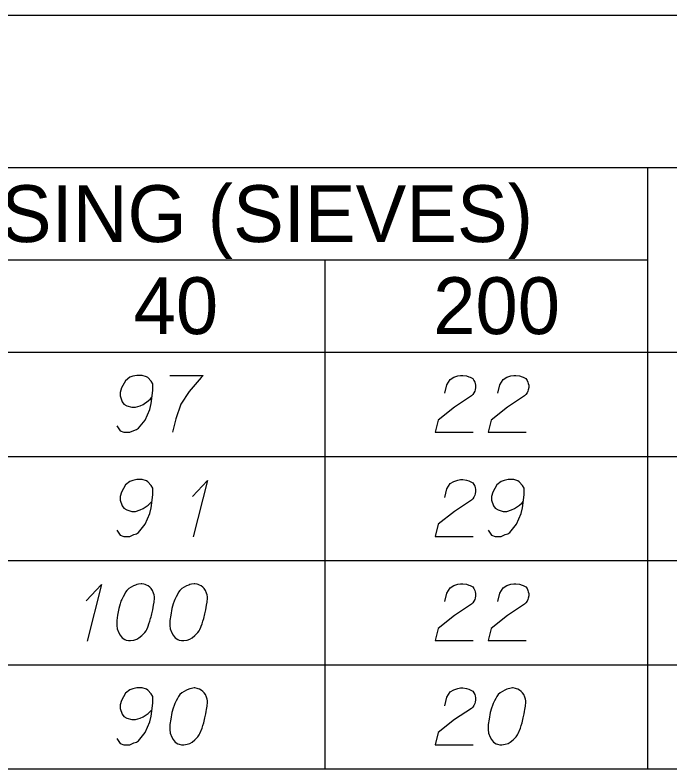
# Model space of a CAD drawing. Extents: x 2074207 to 2076812, y 516372 to 523312.
# Drawn here: x 2076678.5 to 2076733.8, y 516953.6 to 517017.2 of the extents above; entities that cross this region are included whole.
import ezdxf

# ---------------------------------------------------------------- set-up
doc = ezdxf.new("R2010")
doc.units = 0
for name, color, linetype in [('Prop DirtTable_ Soil Test Results - Outline (Major)', 7, 'Continuous'), ('Prop DirtTable_ Soil Test Results - Outline (Minor)', 7, 'Continuous'), ('Prop DirtTable_ Soil Test Results - Tx (Header - Small)', 7, 'Continuous'), ('Prop DirtTable_ Soil Test Results - Tx (Sample Data)', 7, 'Continuous')]:
    doc.layers.add(name, color=color, linetype=linetype)

msp = doc.modelspace()

# ---------------------------------------------------------------- linework, layer by layer
at = {"layer": 'Prop DirtTable_ Soil Test Results - Outline (Major)'}
for p, q in [((2076260.609, 517017.246), (2076811.903, 517017.246)), ((2076260.609, 516988.761), (2076811.903, 516988.761)), ((2076260.609, 516988.761), (2076811.903, 516988.761)), ((2076260.609, 516953.561), (2076811.903, 516953.561))]:
    msp.add_line(p, q, dxfattribs=at)
at = {"layer": 'Prop DirtTable_ Soil Test Results - Outline (Minor)'}
for p, q in [((2076260.609, 517004.361), (2076811.903, 517004.361)), ((2076731.93, 517004.361), (2076731.93, 516979.961)), ((2076526.074, 516996.561), (2076731.93, 516996.561)), ((2076704.671, 516996.561), (2076704.671, 516979.961)), ((2076260.609, 516979.961), (2076811.903, 516979.961)), ((2076260.609, 516979.961), (2076811.903, 516979.961)), ((2076704.671, 516979.961), (2076704.671, 516971.161)), ((2076731.93, 516979.961), (2076731.93, 516971.161)), ((2076260.609, 516971.161), (2076811.903, 516971.161)), ((2076260.609, 516971.161), (2076811.903, 516971.161)), ((2076704.671, 516971.161), (2076704.671, 516962.361)), ((2076731.93, 516971.161), (2076731.93, 516962.361)), ((2076260.609, 516962.361), (2076811.903, 516962.361)), ((2076260.609, 516962.361), (2076811.903, 516962.361)), ((2076704.671, 516962.361), (2076704.671, 516953.561)), ((2076731.93, 516962.361), (2076731.93, 516953.561)), ((2076260.609, 516953.561), (2076811.903, 516953.561))]:
    msp.add_line(p, q, dxfattribs=at)
at = {"layer": 'Prop DirtTable_ Soil Test Results - Tx (Sample Data)'}
for points in [[(2076687.116, 516982.534), (2076687.398, 516982.119), (2076687.715, 516982.005), (2076688.209, 516982.005), (2076688.562, 516982.156), (2076688.774, 516982.232), (2076688.95, 516982.345), (2076689.514, 516983.026), (2076689.902, 516983.933), (2076690.008, 516984.424), (2076690.149, 516985.52), (2076690.149, 516986.087), (2076690.008, 516986.314), (2076689.726, 516986.616), (2076689.62, 516986.692), (2076689.267, 516986.805), (2076688.809, 516986.805), (2076688.456, 516986.73), (2076688.209, 516986.654), (2076687.856, 516986.352), (2076687.504, 516985.747), (2076687.398, 516985.369), (2076687.398, 516985.067), (2076687.574, 516984.575), (2076687.715, 516984.386), (2076687.962, 516984.235), (2076688.386, 516984.122), (2076688.703, 516984.122), (2076689.091, 516984.235), (2076689.338, 516984.348), (2076689.761, 516984.651), (2076689.973, 516984.84), (2076690.079, 516984.953)], [(2076691.596, 516986.805), (2076694.418, 516986.805), (2076694.241, 516986.616), (2076693.218, 516985.444), (2076692.513, 516984.386), (2076692.089, 516983.139), (2076691.807, 516982.005)], [(2076714.807, 516985.293), (2076714.983, 516986.011), (2076715.266, 516986.465), (2076715.583, 516986.654), (2076715.9, 516986.767), (2076716.147, 516986.805), (2076716.324, 516986.805), (2076716.641, 516986.767), (2076716.853, 516986.692), (2076716.959, 516986.654), (2076717.17, 516986.541), (2076717.276, 516986.389), (2076717.347, 516986.238), (2076717.382, 516986.125), (2076717.417, 516985.974), (2076717.417, 516985.785), (2076717.382, 516985.596), (2076717.347, 516985.482), (2076717.276, 516985.331), (2076717.17, 516985.18), (2076717.065, 516985.067), (2076715.618, 516984.122), (2076714.243, 516983.026), (2076713.996, 516982.005), (2076717.206, 516982.005)], [(2076719.287, 516985.293), (2076719.463, 516986.011), (2076719.746, 516986.465), (2076720.063, 516986.654), (2076720.38, 516986.767), (2076720.627, 516986.805), (2076720.804, 516986.805), (2076721.121, 516986.767), (2076721.333, 516986.692), (2076721.439, 516986.654), (2076721.65, 516986.541), (2076721.756, 516986.389), (2076721.827, 516986.238), (2076721.862, 516986.125), (2076721.897, 516985.974), (2076721.897, 516985.785), (2076721.862, 516985.596), (2076721.827, 516985.482), (2076721.756, 516985.331), (2076721.65, 516985.18), (2076721.545, 516985.067), (2076720.098, 516984.122), (2076718.723, 516983.026), (2076718.476, 516982.005), (2076721.686, 516982.005)], [(2076687.116, 516973.734), (2076687.398, 516973.319), (2076687.715, 516973.205), (2076688.209, 516973.205), (2076688.562, 516973.356), (2076688.774, 516973.432), (2076688.95, 516973.545), (2076689.514, 516974.226), (2076689.902, 516975.133), (2076690.008, 516975.624), (2076690.149, 516976.72), (2076690.149, 516977.287), (2076690.008, 516977.514), (2076689.726, 516977.816), (2076689.62, 516977.892), (2076689.267, 516978.005), (2076688.809, 516978.005), (2076688.456, 516977.93), (2076688.209, 516977.854), (2076687.856, 516977.552), (2076687.504, 516976.947), (2076687.398, 516976.569), (2076687.398, 516976.267), (2076687.574, 516975.775), (2076687.715, 516975.586), (2076687.962, 516975.435), (2076688.386, 516975.322), (2076688.703, 516975.322), (2076689.091, 516975.435), (2076689.338, 516975.548), (2076689.761, 516975.851), (2076689.973, 516976.04), (2076690.079, 516976.153)], [(2076693.5, 516976.569), (2076694.77, 516977.93), (2076693.571, 516973.167)], [(2076714.807, 516976.493), (2076714.983, 516977.211), (2076715.266, 516977.665), (2076715.583, 516977.854), (2076715.9, 516977.967), (2076716.147, 516978.005), (2076716.324, 516978.005), (2076716.641, 516977.967), (2076716.853, 516977.892), (2076716.959, 516977.854), (2076717.17, 516977.741), (2076717.276, 516977.589), (2076717.347, 516977.438), (2076717.382, 516977.325), (2076717.417, 516977.174), (2076717.417, 516976.985), (2076717.382, 516976.796), (2076717.347, 516976.682), (2076717.276, 516976.531), (2076717.17, 516976.38), (2076717.065, 516976.267), (2076715.618, 516975.322), (2076714.243, 516974.226), (2076713.996, 516973.205), (2076717.206, 516973.205)], [(2076718.476, 516973.734), (2076718.758, 516973.319), (2076719.075, 516973.205), (2076719.569, 516973.205), (2076719.922, 516973.356), (2076720.134, 516973.432), (2076720.31, 516973.545), (2076720.874, 516974.226), (2076721.262, 516975.133), (2076721.368, 516975.624), (2076721.509, 516976.72), (2076721.509, 516977.287), (2076721.368, 516977.514), (2076721.086, 516977.816), (2076720.98, 516977.892), (2076720.627, 516978.005), (2076720.169, 516978.005), (2076719.816, 516977.93), (2076719.569, 516977.854), (2076719.216, 516977.552), (2076718.864, 516976.947), (2076718.758, 516976.569), (2076718.758, 516976.267), (2076718.934, 516975.775), (2076719.075, 516975.586), (2076719.322, 516975.435), (2076719.746, 516975.322), (2076720.063, 516975.322), (2076720.451, 516975.435), (2076720.698, 516975.548), (2076721.121, 516975.851), (2076721.333, 516976.04), (2076721.439, 516976.153)], [(2076684.54, 516967.769), (2076685.81, 516969.13), (2076684.611, 516964.367)], [(2076689.232, 516969.205), (2076689.162, 516969.205), (2076688.95, 516969.167), (2076688.809, 516969.13), (2076688.703, 516969.092), (2076688.527, 516969.016), (2076688.315, 516968.903), (2076688.139, 516968.789), (2076687.962, 516968.638), (2076687.856, 516968.487), (2076687.751, 516968.298), (2076687.645, 516968.109), (2076687.539, 516967.882), (2076687.468, 516967.731), (2076687.398, 516967.504), (2076687.292, 516967.126), (2076687.186, 516966.559), (2076687.116, 516966.106), (2076687.116, 516965.69), (2076687.151, 516965.388), (2076687.292, 516965.048), (2076687.398, 516964.859), (2076687.574, 516964.632), (2076687.786, 516964.481), (2076687.892, 516964.443), (2076688.103, 516964.405), (2076688.28, 516964.405), (2076688.562, 516964.443), (2076688.809, 516964.519), (2076688.985, 516964.632), (2076689.232, 516964.821), (2076689.338, 516964.934), (2076689.479, 516965.085), (2076689.585, 516965.237), (2076689.655, 516965.35), (2076689.726, 516965.539), (2076689.761, 516965.615), (2076689.832, 516965.804), (2076689.902, 516966.03), (2076689.973, 516966.257), (2076690.008, 516966.408), (2076690.043, 516966.522), (2076690.079, 516966.673), (2076690.149, 516967.013), (2076690.185, 516967.202), (2076690.22, 516967.391), (2076690.255, 516967.656), (2076690.29, 516967.996), (2076690.29, 516968.109), (2076690.255, 516968.26), (2076690.22, 516968.411), (2076690.114, 516968.638), (2076690.008, 516968.789), (2076689.902, 516968.903), (2076689.761, 516969.016), (2076689.62, 516969.092), (2076689.514, 516969.13), (2076689.409, 516969.167), (2076689.232, 516969.205)], [(2076693.712, 516969.205), (2076693.642, 516969.205), (2076693.43, 516969.167), (2076693.289, 516969.13), (2076693.183, 516969.092), (2076693.007, 516969.016), (2076692.795, 516968.903), (2076692.619, 516968.789), (2076692.442, 516968.638), (2076692.336, 516968.487), (2076692.231, 516968.298), (2076692.125, 516968.109), (2076692.019, 516967.882), (2076691.948, 516967.731), (2076691.878, 516967.504), (2076691.772, 516967.126), (2076691.666, 516966.559), (2076691.596, 516966.106), (2076691.596, 516965.69), (2076691.631, 516965.388), (2076691.772, 516965.048), (2076691.878, 516964.859), (2076692.054, 516964.632), (2076692.266, 516964.481), (2076692.372, 516964.443), (2076692.583, 516964.405), (2076692.76, 516964.405), (2076693.042, 516964.443), (2076693.289, 516964.519), (2076693.465, 516964.632), (2076693.712, 516964.821), (2076693.818, 516964.934), (2076693.959, 516965.085), (2076694.065, 516965.237), (2076694.135, 516965.35), (2076694.206, 516965.539), (2076694.241, 516965.615), (2076694.312, 516965.804), (2076694.382, 516966.03), (2076694.453, 516966.257), (2076694.488, 516966.408), (2076694.523, 516966.522), (2076694.559, 516966.673), (2076694.629, 516967.013), (2076694.665, 516967.202), (2076694.7, 516967.391), (2076694.735, 516967.656), (2076694.77, 516967.996), (2076694.77, 516968.109), (2076694.735, 516968.26), (2076694.7, 516968.411), (2076694.594, 516968.638), (2076694.488, 516968.789), (2076694.382, 516968.903), (2076694.241, 516969.016), (2076694.1, 516969.092), (2076693.994, 516969.13), (2076693.889, 516969.167), (2076693.712, 516969.205)], [(2076714.807, 516967.693), (2076714.983, 516968.411), (2076715.266, 516968.865), (2076715.583, 516969.054), (2076715.9, 516969.167), (2076716.147, 516969.205), (2076716.324, 516969.205), (2076716.641, 516969.167), (2076716.853, 516969.092), (2076716.959, 516969.054), (2076717.17, 516968.941), (2076717.276, 516968.789), (2076717.347, 516968.638), (2076717.382, 516968.525), (2076717.417, 516968.374), (2076717.417, 516968.185), (2076717.382, 516967.996), (2076717.347, 516967.882), (2076717.276, 516967.731), (2076717.17, 516967.58), (2076717.065, 516967.467), (2076715.618, 516966.522), (2076714.243, 516965.426), (2076713.996, 516964.405), (2076717.206, 516964.405)], [(2076719.287, 516967.693), (2076719.463, 516968.411), (2076719.746, 516968.865), (2076720.063, 516969.054), (2076720.38, 516969.167), (2076720.627, 516969.205), (2076720.804, 516969.205), (2076721.121, 516969.167), (2076721.333, 516969.092), (2076721.439, 516969.054), (2076721.65, 516968.941), (2076721.756, 516968.789), (2076721.827, 516968.638), (2076721.862, 516968.525), (2076721.897, 516968.374), (2076721.897, 516968.185), (2076721.862, 516967.996), (2076721.827, 516967.882), (2076721.756, 516967.731), (2076721.65, 516967.58), (2076721.545, 516967.467), (2076720.098, 516966.522), (2076718.723, 516965.426), (2076718.476, 516964.405), (2076721.686, 516964.405)], [(2076687.116, 516956.134), (2076687.398, 516955.719), (2076687.715, 516955.605), (2076688.209, 516955.605), (2076688.562, 516955.756), (2076688.774, 516955.832), (2076688.95, 516955.945), (2076689.514, 516956.626), (2076689.902, 516957.533), (2076690.008, 516958.024), (2076690.149, 516959.12), (2076690.149, 516959.687), (2076690.008, 516959.914), (2076689.726, 516960.216), (2076689.62, 516960.292), (2076689.267, 516960.405), (2076688.809, 516960.405), (2076688.456, 516960.33), (2076688.209, 516960.254), (2076687.856, 516959.952), (2076687.504, 516959.347), (2076687.398, 516958.969), (2076687.398, 516958.667), (2076687.574, 516958.175), (2076687.715, 516957.986), (2076687.962, 516957.835), (2076688.386, 516957.722), (2076688.703, 516957.722), (2076689.091, 516957.835), (2076689.338, 516957.948), (2076689.761, 516958.251), (2076689.973, 516958.44), (2076690.079, 516958.553)], [(2076693.712, 516960.405), (2076693.642, 516960.405), (2076693.43, 516960.367), (2076693.289, 516960.33), (2076693.183, 516960.292), (2076693.007, 516960.216), (2076692.795, 516960.103), (2076692.619, 516959.989), (2076692.442, 516959.838), (2076692.336, 516959.687), (2076692.231, 516959.498), (2076692.125, 516959.309), (2076692.019, 516959.082), (2076691.948, 516958.931), (2076691.878, 516958.704), (2076691.772, 516958.326), (2076691.666, 516957.759), (2076691.596, 516957.306), (2076691.596, 516956.89), (2076691.631, 516956.588), (2076691.772, 516956.248), (2076691.878, 516956.059), (2076692.054, 516955.832), (2076692.266, 516955.681), (2076692.372, 516955.643), (2076692.583, 516955.605), (2076692.76, 516955.605), (2076693.042, 516955.643), (2076693.289, 516955.719), (2076693.465, 516955.832), (2076693.712, 516956.021), (2076693.818, 516956.134), (2076693.959, 516956.285), (2076694.065, 516956.437), (2076694.135, 516956.55), (2076694.206, 516956.739), (2076694.241, 516956.815), (2076694.312, 516957.004), (2076694.382, 516957.23), (2076694.453, 516957.457), (2076694.488, 516957.608), (2076694.523, 516957.722), (2076694.559, 516957.873), (2076694.629, 516958.213), (2076694.665, 516958.402), (2076694.7, 516958.591), (2076694.735, 516958.856), (2076694.77, 516959.196), (2076694.77, 516959.309), (2076694.735, 516959.46), (2076694.7, 516959.611), (2076694.594, 516959.838), (2076694.488, 516959.989), (2076694.382, 516960.103), (2076694.241, 516960.216), (2076694.1, 516960.292), (2076693.994, 516960.33), (2076693.889, 516960.367), (2076693.712, 516960.405)], [(2076714.807, 516958.893), (2076714.983, 516959.611), (2076715.266, 516960.065), (2076715.583, 516960.254), (2076715.9, 516960.367), (2076716.147, 516960.405), (2076716.324, 516960.405), (2076716.641, 516960.367), (2076716.853, 516960.292), (2076716.959, 516960.254), (2076717.17, 516960.141), (2076717.276, 516959.989), (2076717.347, 516959.838), (2076717.382, 516959.725), (2076717.417, 516959.574), (2076717.417, 516959.385), (2076717.382, 516959.196), (2076717.347, 516959.082), (2076717.276, 516958.931), (2076717.17, 516958.78), (2076717.065, 516958.667), (2076715.618, 516957.722), (2076714.243, 516956.626), (2076713.996, 516955.605), (2076717.206, 516955.605)], [(2076720.592, 516960.405), (2076720.522, 516960.405), (2076720.31, 516960.367), (2076720.169, 516960.33), (2076720.063, 516960.292), (2076719.887, 516960.216), (2076719.675, 516960.103), (2076719.499, 516959.989), (2076719.322, 516959.838), (2076719.216, 516959.687), (2076719.111, 516959.498), (2076719.005, 516959.309), (2076718.899, 516959.082), (2076718.828, 516958.931), (2076718.758, 516958.704), (2076718.652, 516958.326), (2076718.546, 516957.759), (2076718.476, 516957.306), (2076718.476, 516956.89), (2076718.511, 516956.588), (2076718.652, 516956.248), (2076718.758, 516956.059), (2076718.934, 516955.832), (2076719.146, 516955.681), (2076719.252, 516955.643), (2076719.463, 516955.605), (2076719.64, 516955.605), (2076719.922, 516955.643), (2076720.169, 516955.719), (2076720.345, 516955.832), (2076720.592, 516956.021), (2076720.698, 516956.134), (2076720.839, 516956.285), (2076720.945, 516956.437), (2076721.015, 516956.55), (2076721.086, 516956.739), (2076721.121, 516956.815), (2076721.192, 516957.004), (2076721.262, 516957.23), (2076721.333, 516957.457), (2076721.368, 516957.608), (2076721.403, 516957.722), (2076721.439, 516957.873), (2076721.509, 516958.213), (2076721.545, 516958.402), (2076721.58, 516958.591), (2076721.615, 516958.856), (2076721.65, 516959.196), (2076721.65, 516959.309), (2076721.615, 516959.46), (2076721.58, 516959.611), (2076721.474, 516959.838), (2076721.368, 516959.989), (2076721.262, 516960.103), (2076721.121, 516960.216), (2076720.98, 516960.292), (2076720.874, 516960.33), (2076720.769, 516960.367), (2076720.592, 516960.405)]]:
    msp.add_lwpolyline(points, dxfattribs=at)

# ---------------------------------------------------------------- texts
at = {"layer": 'Prop DirtTable_ Soil Test Results - Tx (Header - Small)'}
for s, height, p in [('% PASSING (SIEVES)', 4.79998, (2076656.984, 516998.071)), ('40', 4.8, (2076688.534, 516990.296)), ('200', 4.8, (2076713.832, 516990.296))]:
    msp.add_text(s, height=height, dxfattribs=at).set_placement(p)

doc.saveas('drawing.dxf')
